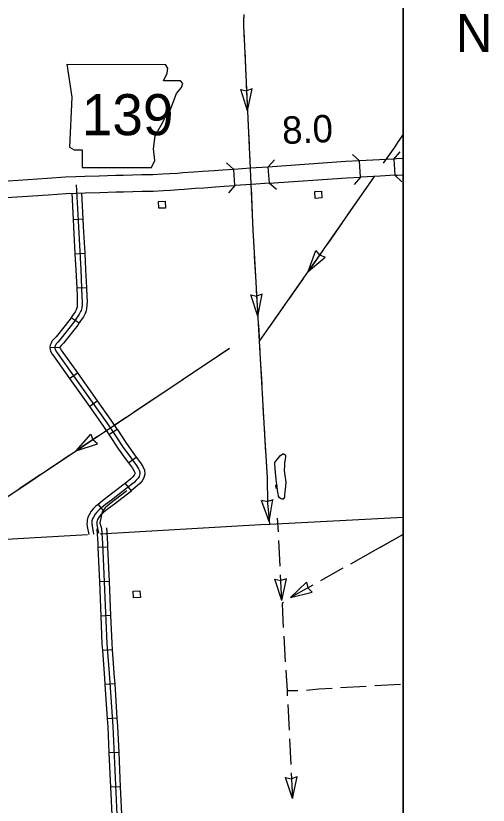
# Model space of a CAD drawing. Extents: x -0.3 to 2.65, y 0 to 1.9.
# Drawn here: x 0.9604 to 1.0476, y 0.3171 to 0.4627 of the extents above; entities that cross this region are included whole.
import ezdxf

# ---------------------------------------------------------------- set-up
doc = ezdxf.new("R2010")
doc.units = 0
for name, color, linetype in [('DSN_DRFT_DNC', 7, 'Continuous'), ('Level 12', 7, 'Continuous'), ('Level 14', 7, 'Continuous'), ('Level 15', 7, 'Continuous'), ('Level 16', 7, 'Continuous'), ('Level 19', 7, 'Continuous'), ('Level 21', 7, 'Continuous'), ('Level 22', 7, 'Continuous'), ('Level 23', 7, 'Continuous'), ('Level 30', 7, 'Continuous'), ('Level 6', 7, 'Continuous'), ('SHET_Annotations', 7, 'Continuous')]:
    doc.layers.add(name, color=color, linetype=linetype)

msp = doc.modelspace()

# ---------------------------------------------------------------- linework, layer by layer
at = {"layer": 'DSN_DRFT_DNC'}
msp.add_lwpolyline([(0.38477, 0.54167), (1.0319, 0.54167), (1.0319, 0.1443), (0.38477, 0.1443)], close=True, dxfattribs=at)
at = {"layer": 'Level 12'}
for p, q in [((1.00318, 0.44515), (1.00194, 0.44906)), ((1.00194, 0.44906), (1.003, 0.44883)), ((1.00406, 0.44916), (1.00302, 0.44883)), ((1.00318, 0.44515), (1.00406, 0.44916)), ((1.01437, 0.41552), (1.01578, 0.41938)), ((1.01578, 0.41938), (1.01648, 0.41854)), ((1.01437, 0.41552), (1.01752, 0.41816)), ((1.01752, 0.41816), (1.01649, 0.41853)), ((1.00508, 0.40729), (1.00379, 0.41119)), ((1.00379, 0.41119), (1.00486, 0.41097)), ((1.00591, 0.41131), (1.00487, 0.41097)), ((1.00508, 0.40729), (1.00591, 0.41131)), ((0.9716, 0.38245), (0.97431, 0.38554)), ((0.97431, 0.38554), (0.97466, 0.3845)), ((0.97549, 0.38377), (0.97467, 0.38449)), ((0.9716, 0.38245), (0.97549, 0.38377)), ((1.00719, 0.36945), (1.00575, 0.37329)), ((1.0058, 0.37338), (1.00686, 0.37312)), ((1.00793, 0.37342), (1.00688, 0.37312)), ((1.00719, 0.36945), (1.00786, 0.3735)), ((1.00824, 0.35877), (1.00931, 0.35855)), ((1.0095, 0.35487), (1.00824, 0.35877)), ((1.01036, 0.35888), (1.00932, 0.35855)), ((1.0095, 0.35487), (1.01036, 0.35888)), ((1.01113, 0.3554), (1.01407, 0.35826)), ((1.01407, 0.35826), (1.01434, 0.3572)), ((1.01511, 0.35641), (1.01434, 0.35719)), ((1.01113, 0.3554), (1.01511, 0.35641)), ((1.01022, 0.32224), (1.01129, 0.32201)), ((1.01148, 0.31833), (1.01022, 0.32224)), ((1.01234, 0.32234), (1.0113, 0.32201)), ((1.01148, 0.31833), (1.01234, 0.32234))]:
    msp.add_line(p, q, dxfattribs=at)
for points in [[(1.0025, 0.46291), (1.00244, 0.46192), (1.00247, 0.46062), (1.0025, 0.4597), (1.00375, 0.43311), (1.00419, 0.42315), (1.00439, 0.41898), (1.00535, 0.4027), (1.00638, 0.38437), (1.00664, 0.38053), (1.00678, 0.37749), (1.00688, 0.37276), (1.00698, 0.37161), (1.00724, 0.36891)], [(1.00248, 0.46251), (1.00244, 0.46192), (1.00247, 0.46062), (1.0025, 0.4597), (1.00259, 0.45777)], [(1.00266, 0.4562), (1.00289, 0.45146)], [(1.00296, 0.44988), (1.00318, 0.44515)], [(1.00326, 0.44357), (1.00337, 0.44121)], [(1.00337, 0.44121), (1.00348, 0.43884)], [(1.03189, 0.44081), (1.03085, 0.43931), (1.03036, 0.43851), (1.02823, 0.43549)], [(1.03138, 0.44007), (1.03085, 0.43931), (1.03036, 0.43851), (1.0287, 0.43616)], [(1.00356, 0.43726), (1.00369, 0.43454)], [(1.02652, 0.43304), (1.01784, 0.42047), (1.00535, 0.4027)], [(1.02652, 0.43304), (1.02518, 0.43109)], [(1.00385, 0.43095), (1.00405, 0.42622)], [(1.02428, 0.42979), (1.02159, 0.42589)], [(1.00412, 0.42464), (1.00419, 0.42315), (1.00434, 0.41991)], [(1.02069, 0.42459), (1.018, 0.42069)], [(1.01709, 0.4194), (1.01437, 0.41552)], [(1.00443, 0.41833), (1.00471, 0.4136)], [(1.01346, 0.41423), (1.01073, 0.41036)], [(1.0048, 0.41202), (1.00508, 0.40729)], [(1.00983, 0.40906), (1.0071, 0.40519)], [(1.00518, 0.40571), (1.00532, 0.40335)], [(1.00532, 0.40335), (1.00535, 0.4027), (1.00545, 0.40098)], [(1.00619, 0.40389), (1.00535, 0.4027)], [(0.99984, 0.40132), (0.94649, 0.36567)], [(0.99984, 0.40132), (0.99787, 0.4)], [(0.99655, 0.39912), (0.99261, 0.39649)], [(1.00554, 0.39941), (1.0058, 0.39468)], [(0.9913, 0.39561), (0.98736, 0.39298)], [(1.00589, 0.3931), (1.00615, 0.38837)], [(0.98605, 0.3921), (0.98211, 0.38947)], [(0.98079, 0.38859), (0.97864, 0.38716)], [(1.00624, 0.38679), (1.00638, 0.38437), (1.00653, 0.38206)], [(0.97554, 0.38508), (0.9716, 0.38245)], [(0.97029, 0.38157), (0.96832, 0.38026)], [(0.96832, 0.38026), (0.96635, 0.37894)], [(1.00664, 0.38048), (1.00678, 0.37749), (1.00682, 0.37575)], [(0.96503, 0.37806), (0.96109, 0.37543)], [(1.00685, 0.37417), (1.00688, 0.37276), (1.00698, 0.37161), (1.00719, 0.36945)], [(1.00867, 0.37003), (1.00881, 0.36749)], [(1.0318, 0.36697), (1.02767, 0.36466)], [(1.00889, 0.36591), (1.00914, 0.36118)], [(1.02629, 0.36388), (1.02215, 0.36157)], [(1.00923, 0.3596), (1.00948, 0.35487)], [(1.02077, 0.3608), (1.01664, 0.35848)], [(1.01526, 0.35771), (1.01113, 0.3554)], [(1.00984, 0.35449), (1.0096, 0.35429), (1.00961, 0.35272), (1.00978, 0.34987)], [(1.00987, 0.3483), (1.01015, 0.34357)], [(1.01025, 0.34199), (1.01047, 0.3382), (1.01052, 0.33726)], [(1.0314, 0.3394), (1.02667, 0.33912)], [(1.01249, 0.33822), (1.01047, 0.3382)], [(1.01879, 0.33865), (1.01636, 0.33851), (1.01406, 0.33828)], [(1.02509, 0.33903), (1.02036, 0.33875)], [(1.0106, 0.33568), (1.01084, 0.33095)], [(1.01092, 0.32937), (1.01116, 0.32464)], [(1.01124, 0.32306), (1.01148, 0.31833)]]:
    msp.add_lwpolyline(points, dxfattribs=at)
at = {"layer": 'Level 14'}
msp.add_line((1.03189, 0.36702), (1.02618, 0.36382), dxfattribs=at)
msp.add_line((1.03189, 0.36702), (1.02618, 0.36382), dxfattribs=at)
for points in [[(1.00849, 0.37718), (1.00836, 0.37843), (1.00821, 0.37998), (1.00824, 0.3803), (1.00862, 0.38082), (1.00924, 0.38161), (1.00971, 0.38193), (1.0099, 0.38193), (1.01015, 0.38172), (1.0102, 0.38151), (1.0102, 0.38126), (1.0101, 0.38091), (1.01, 0.38026), (1.01, 0.37975)], [(1.01, 0.37975), (1.00995, 0.37882), (1.01005, 0.3779), (1.01024, 0.37668), (1.01011, 0.37534), (1.01, 0.37437), (1.00998, 0.3739), (1.0099, 0.37372), (1.00976, 0.37356), (1.00959, 0.37356), (1.0094, 0.37359), (1.00911, 0.37378), (1.00888, 0.37412), (1.00881, 0.37456), (1.00873, 0.37513), (1.00867, 0.37593), (1.00855, 0.37665), (1.00849, 0.37718)], [(1.00835, 0.37616), (1.00839, 0.37548)], [(1.00835, 0.37616), (1.00839, 0.37548)]]:
    msp.add_lwpolyline(points, dxfattribs=at)
at = {"layer": 'Level 15'}
for p, q in [((0.97102, 0.42512), (0.97281, 0.42521)), ((0.97136, 0.4188), (0.97315, 0.4189)), ((0.97167, 0.4125), (0.97346, 0.41258)), ((0.97068, 0.40706), (0.97216, 0.40604)), ((0.96674, 0.40159), (0.96853, 0.40149)), ((0.97036, 0.39578), (0.97182, 0.39682)), ((0.97401, 0.39063), (0.97548, 0.39167)), ((0.97761, 0.38547), (0.97911, 0.38646)), ((0.98124, 0.38023), (0.98267, 0.38131)), ((0.9806, 0.37645), (0.98173, 0.37506)), ((0.97561, 0.37258), (0.97674, 0.37119)), ((0.97737, 0.36469), (0.97558, 0.36461)), ((0.97764, 0.35838), (0.97585, 0.3583)), ((0.97791, 0.35207), (0.97612, 0.35199)), ((0.97822, 0.34579), (0.97643, 0.34565)), ((0.97869, 0.33948), (0.97689, 0.33936)), ((0.9791, 0.33317), (0.97731, 0.33305)), ((0.97942, 0.32684), (0.97762, 0.32676)), ((0.9797, 0.32053), (0.97791, 0.32045))]:
    msp.add_line(p, q, dxfattribs=at)
for points in [[(0.97158, 0.43147), (0.97199, 0.42376), (0.97242, 0.41581), (0.97264, 0.41087), (0.97268, 0.40997), (0.97267, 0.40938), (0.97262, 0.4088), (0.97248, 0.40835), (0.9724, 0.40811), (0.97214, 0.40763), (0.97166, 0.40689), (0.97116, 0.40617), (0.96856, 0.4029), (0.96817, 0.40247), (0.96789, 0.40217), (0.9678, 0.40202), (0.96775, 0.40192), (0.96764, 0.40171), (0.96763, 0.40149), (0.96765, 0.40133), (0.96769, 0.40118), (0.96791, 0.40076), (0.9681, 0.4005), (0.97726, 0.3876), (0.97827, 0.3861), (0.98013, 0.38328), (0.98134, 0.38159), (0.98272, 0.37976), (0.98309, 0.37913), (0.98332, 0.37865), (0.98333, 0.37824), (0.98326, 0.37798), (0.98317, 0.37771), (0.98302, 0.37742), (0.98266, 0.37703), (0.98225, 0.37664), (0.98101, 0.37562), (0.9781, 0.37336), (0.97699, 0.37255), (0.97582, 0.3716), (0.97538, 0.37115), (0.97511, 0.37079), (0.97475, 0.37024), (0.97458, 0.36989), (0.97448, 0.36954), (0.97447, 0.36931), (0.97446, 0.36904), (0.9745, 0.36865), (0.9748, 0.36711)], [(0.97076, 0.42995), (0.97102, 0.42512)], [(0.97256, 0.43), (0.97281, 0.42521)], [(0.97102, 0.42512), (0.97109, 0.42372), (0.97136, 0.4188)], [(0.97281, 0.42521), (0.97288, 0.42381), (0.97315, 0.4189)], [(0.97136, 0.4188), (0.97152, 0.41577), (0.97167, 0.4125)], [(0.97315, 0.4189), (0.97331, 0.41586), (0.97346, 0.41258)], [(0.97167, 0.4125), (0.97174, 0.41082), (0.97178, 0.40996), (0.97177, 0.40942), (0.97174, 0.40897), (0.97163, 0.40863), (0.97157, 0.40846), (0.97137, 0.40808), (0.97091, 0.40739), (0.97068, 0.40706)], [(0.97346, 0.41258), (0.97353, 0.41091), (0.97358, 0.40998), (0.97356, 0.40933), (0.97351, 0.40862), (0.97333, 0.40807), (0.97323, 0.40775), (0.97291, 0.40717), (0.9724, 0.40639), (0.97216, 0.40604)], [(0.97068, 0.40706), (0.97044, 0.40671), (0.96788, 0.40348), (0.96752, 0.40308), (0.96717, 0.40271), (0.96702, 0.40247), (0.96695, 0.40233), (0.96676, 0.40194), (0.96674, 0.40159)], [(0.97216, 0.40604), (0.97188, 0.40564), (0.96925, 0.40232), (0.96883, 0.40187), (0.96861, 0.40162), (0.96858, 0.40158), (0.96854, 0.40151), (0.96853, 0.40148), (0.96853, 0.40149)], [(0.96674, 0.40159), (0.96673, 0.40146), (0.96677, 0.40116), (0.96685, 0.40084), (0.96715, 0.40028), (0.96738, 0.39998), (0.97036, 0.39578)], [(0.96853, 0.40151), (0.96853, 0.40151), (0.96867, 0.40124), (0.96883, 0.40103), (0.97182, 0.39682)], [(0.97182, 0.39682), (0.97548, 0.39167)], [(0.97036, 0.39578), (0.97401, 0.39063)], [(0.97548, 0.39167), (0.978, 0.38811), (0.97902, 0.38659), (0.97911, 0.38646)], [(0.97401, 0.39063), (0.97652, 0.3871), (0.97752, 0.3856), (0.97761, 0.38547)], [(0.97911, 0.38646), (0.98087, 0.38379), (0.98206, 0.38212), (0.98267, 0.38131)], [(0.97761, 0.38547), (0.97939, 0.38278), (0.98061, 0.38106), (0.98124, 0.38023)], [(0.98267, 0.38131), (0.98347, 0.38026), (0.98389, 0.37955), (0.98421, 0.37886), (0.98423, 0.37813), (0.98412, 0.37772), (0.984, 0.37736), (0.98376, 0.3769), (0.98329, 0.3764), (0.98285, 0.37597), (0.98173, 0.37506)], [(0.98124, 0.38023), (0.98198, 0.37925), (0.9823, 0.37871), (0.98242, 0.37844), (0.98243, 0.37835), (0.9824, 0.37824), (0.98234, 0.37806), (0.98227, 0.37794), (0.98202, 0.37766), (0.98166, 0.37732), (0.9806, 0.37645)], [(0.9806, 0.37645), (0.98045, 0.37633), (0.97756, 0.37408), (0.97645, 0.37326), (0.97561, 0.37258)], [(0.98091, 0.37508), (0.9778, 0.37269), (0.97694, 0.37197), (0.97639, 0.37118), (0.97616, 0.37034), (0.97597, 0.36919), (0.97628, 0.36815), (0.97646, 0.36534), (0.97725, 0.34693), (0.97773, 0.34062), (0.97832, 0.33161), (0.97955, 0.3046)], [(0.98173, 0.37506), (0.98157, 0.37492), (0.97864, 0.37264), (0.97754, 0.37184), (0.97674, 0.37119)], [(0.97561, 0.37258), (0.97521, 0.37226), (0.9747, 0.37174), (0.97437, 0.3713), (0.97396, 0.37068), (0.97373, 0.37021), (0.97359, 0.36968), (0.97358, 0.36935), (0.97357, 0.36901), (0.97361, 0.36852), (0.9739, 0.36705)], [(0.97674, 0.37119), (0.97642, 0.37093), (0.97606, 0.37057), (0.97584, 0.37027), (0.97553, 0.36979), (0.97542, 0.36957), (0.97538, 0.3694), (0.97537, 0.36928), (0.97536, 0.36907), (0.97539, 0.36878), (0.97568, 0.36728)], [(0.97716, 0.36824), (0.97734, 0.36538), (0.97737, 0.36469)], [(0.97533, 0.36813), (0.97537, 0.36799), (0.97555, 0.36529), (0.97558, 0.36461)], [(0.97558, 0.36461), (0.97585, 0.3583)], [(0.97737, 0.36469), (0.97764, 0.35838)], [(0.97585, 0.3583), (0.97612, 0.35199)], [(0.97764, 0.35838), (0.97791, 0.35207)], [(0.97612, 0.35199), (0.97634, 0.34688), (0.97643, 0.34565)], [(0.97791, 0.35207), (0.97813, 0.34698), (0.97822, 0.34579)], [(0.97643, 0.34565), (0.97682, 0.34056), (0.97689, 0.33936)], [(0.97822, 0.34579), (0.97861, 0.34068), (0.97869, 0.33948)], [(0.97689, 0.33936), (0.97731, 0.33305)], [(0.97869, 0.33948), (0.9791, 0.33317)], [(0.97731, 0.33305), (0.97741, 0.33156), (0.97762, 0.32676)], [(0.9791, 0.33317), (0.9792, 0.33166), (0.97942, 0.32684)], [(0.97762, 0.32676), (0.97791, 0.32045)], [(0.97942, 0.32684), (0.9797, 0.32053)], [(0.97791, 0.32045), (0.9782, 0.31414)], [(0.9797, 0.32053), (0.97999, 0.31422)]]:
    msp.add_lwpolyline(points, dxfattribs=at)
at = {"layer": 'Level 19'}
for points in [[(1.01564, 0.429), (1.01558, 0.43025), (1.01683, 0.43031), (1.01689, 0.42907)], [(0.9868, 0.42716), (0.98675, 0.4284), (0.988, 0.42845), (0.98805, 0.42721)], [(0.98217, 0.35533), (0.98208, 0.35657), (0.98332, 0.35666), (0.98342, 0.35542)]]:
    msp.add_lwpolyline(points, close=True, dxfattribs=at)
at = {"layer": 'Level 21'}
for points in [[(1.02403, 0.43291), (1.02387, 0.4359), (1.02131, 0.43577), (1.00696, 0.43477)], [(1.03018, 0.43623), (1.02752, 0.43609), (1.02387, 0.4359)], [(1.03189, 0.43634), (1.03066, 0.43626), (1.03018, 0.43623)], [(1.03018, 0.43623), (1.03034, 0.43325), (1.03083, 0.43327), (1.03189, 0.43334)], [(1.00086, 0.43136), (1.00066, 0.43434), (0.99865, 0.43421), (0.99704, 0.43408), (0.99495, 0.43395), (0.99328, 0.43385), (0.99125, 0.43368), (0.99024, 0.4336), (0.98882, 0.43351), (0.98753, 0.43344), (0.9857, 0.43334), (0.98368, 0.43333), (0.98027, 0.4332), (0.97887, 0.4332), (0.97583, 0.43308), (0.97315, 0.43302), (0.97154, 0.43297), (0.96959, 0.4329), (0.96623, 0.43265), (0.95368, 0.43181)], [(1.00696, 0.43477), (1.00371, 0.43454), (1.00066, 0.43434)], [(1.00696, 0.43477), (1.00717, 0.43178), (1.02149, 0.43278), (1.02403, 0.43291)], [(1.03034, 0.43325), (1.02767, 0.4331), (1.02403, 0.43291)], [(0.94131, 0.42799), (0.94426, 0.42814), (0.95389, 0.42882), (0.96644, 0.42967), (0.96975, 0.42991), (0.97163, 0.42998), (0.97323, 0.43003), (0.97592, 0.43009), (0.97893, 0.4302), (0.98033, 0.4302), (0.98375, 0.43033), (0.98579, 0.43035), (0.98769, 0.43045), (0.989, 0.43052), (0.99045, 0.43062), (0.99149, 0.4307), (0.9935, 0.43087), (0.99513, 0.43096), (0.99726, 0.4311), (0.99887, 0.43123), (1.00086, 0.43136)], [(1.00717, 0.43178), (1.00391, 0.43156), (1.00086, 0.43136)]]:
    msp.add_lwpolyline(points, dxfattribs=at)
at = {"layer": 'Level 22'}
for p, q in [((0.96987, 0.45371), (0.97078, 0.44763)), ((0.98849, 0.453), (0.98807, 0.4537)), ((0.98839, 0.45209), (0.98849, 0.453)), ((0.98768, 0.45067), (0.98839, 0.45209)), ((0.99082, 0.45067), (0.98768, 0.45067)), ((0.99123, 0.45016), (0.99082, 0.45067)), ((0.99102, 0.44946), (0.99123, 0.45016)), ((0.98961, 0.44703), (0.99011, 0.44834)), ((0.99011, 0.44834), (0.99102, 0.44946)), ((0.97078, 0.44763), (0.97037, 0.43842)), ((0.989, 0.44541), (0.98961, 0.44703)), ((0.98799, 0.44389), (0.989, 0.44541)), ((0.98728, 0.44247), (0.98799, 0.44389)), ((0.98616, 0.44055), (0.98728, 0.44247)), ((0.98586, 0.43812), (0.98616, 0.44055)), ((0.97037, 0.43842), (0.97118, 0.43792)), ((0.98606, 0.43599), (0.98586, 0.43812)), ((0.97118, 0.43792), (0.9727, 0.43792)), ((0.9727, 0.43792), (0.9727, 0.43468)), ((0.98546, 0.43468), (0.98606, 0.43599)), ((0.9727, 0.43468), (0.98546, 0.43468))]:
    msp.add_line(p, q, dxfattribs=at)
msp.add_lwpolyline([(0.96987, 0.45371), (0.98807, 0.4537)], dxfattribs=at)
at = {"layer": 'Level 23'}
for points in [[(0.97599, 0.36718), (1.0056, 0.36888), (1.00729, 0.36892), (1.03189, 0.37023)], [(0.94468, 0.36538), (0.97369, 0.36705)]]:
    msp.add_lwpolyline(points, dxfattribs=at)
at = {"layer": 'Level 30'}
for points in [[(1.02254, 0.4371), (1.02387, 0.4359)], [(1.03017, 0.43623), (1.03137, 0.43757)], [(0.99931, 0.43553), (1.00066, 0.43434)], [(1.00696, 0.43477), (1.00814, 0.43612)], [(1.02403, 0.43291), (1.02283, 0.43158)], [(1.03168, 0.43205), (1.03034, 0.43325)], [(1.00086, 0.43136), (0.99967, 0.43001)], [(1.00852, 0.43061), (1.00717, 0.43178)]]:
    msp.add_lwpolyline(points, dxfattribs=at)
at = {"layer": 'Level 6'}
msp.add_line((1.03189, 0.14427), (1.03189, 0.54164), dxfattribs=at)

# ---------------------------------------------------------------- texts
at = {"layer": 'Level 16'}
msp.add_text('8.0', height=0.00505, rotation=2.4662, dxfattribs=at).set_placement((1.00966, 0.439))
at = {"layer": 'Level 22'}
msp.add_text('139', height=0.007582, dxfattribs=at).set_placement((0.97261, 0.44064))
at = {"layer": 'SHET_Annotations'}
msp.add_text('N', height=0.007, dxfattribs=at).set_placement((1.04159, 0.45596))

doc.saveas('drawing.dxf')
